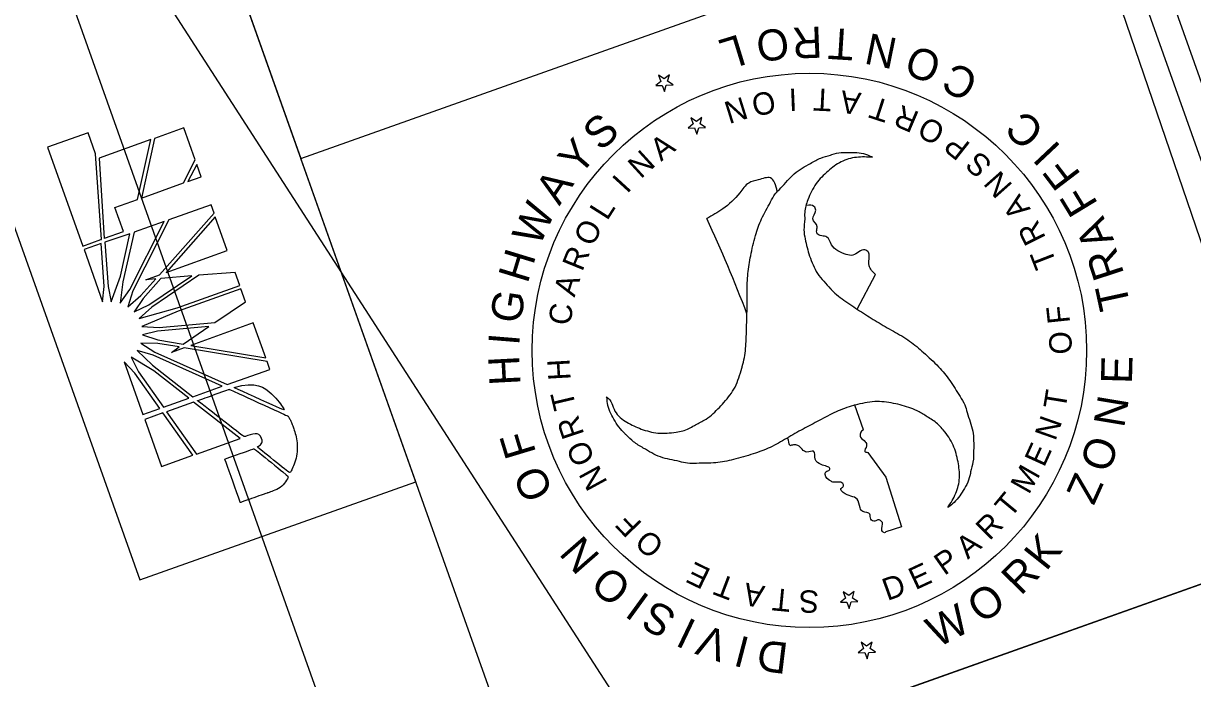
# Model space of a CAD drawing. Extents: x 1615843 to 1618439, y 899470 to 903922.
# Drawn here: x 1616766.4 to 1616956.1, y 903530.7 to 903637 of the extents above; entities that cross this region are included whole.
import ezdxf

# ---------------------------------------------------------------- set-up
doc = ezdxf.new("R2010")
doc.units = 0
for name, color, linetype in [('Default', 7, 'Continuous'), ('DEV BORDER CELL', 7, 'Continuous'), ('DEV DOT SWIRL SEAL CELL', 7, 'Continuous'), ('Scratch_Level_0', 7, 'Continuous'), ('Scratch_Level_5', 7, 'Continuous'), ('Sheet Clip Boundary CELL', 7, 'Continuous'), ('Sheet Plan CELL', 7, 'Continuous'), ('Text', 7, 'Continuous')]:
    doc.layers.add(name, color=color, linetype=linetype)

msp = doc.modelspace()

# ---------------------------------------------------------------- linework, layer by layer
at = {"layer": 'Default'}
for p, q in [((1616776.9, 903619.28), (1616770.33, 903616.94)), ((1616778.12, 903615.87), (1616776.9, 903619.28)), ((1616792.44, 903620.07), (1616787.7, 903618.38)), ((1616794.28, 903614.89), (1616792.44, 903620.07)), ((1616770.33, 903616.94), (1616776.05, 903600.9)), ((1616787.11, 903618.17), (1616778.69, 903615.17)), ((1616784.92, 903608.48), (1616787.11, 903618.17)), ((1616787.7, 903618.38), (1616785.55, 903608.7)), ((1616779.08, 903601.99), (1616778.12, 903615.87)), ((1616778.69, 903615.17), (1616779.53, 903602.15)), ((1616792.37, 903611.14), (1616794.28, 903614.89)), ((1616794.55, 903614.14), (1616793.11, 903611.4)), ((1616795.25, 903612.16), (1616794.55, 903614.14)), ((1616793.11, 903611.4), (1616795.25, 903612.16)), ((1616785.55, 903608.7), (1616792.37, 903611.14)), ((1616781.26, 903607.17), (1616784.92, 903608.48)), ((1616796.88, 903607.61), (1616790.03, 903605.17)), ((1616797.36, 903606.26), (1616796.88, 903607.61)), ((1616782.65, 903603.26), (1616781.26, 903607.17)), ((1616788.48, 903596.23), (1616797.36, 903606.26)), ((1616797.54, 903605.62), (1616789.57, 903596.62)), ((1616799.49, 903600.16), (1616797.54, 903605.62)), ((1616783.68, 903593.85), (1616789.24, 903604.88)), ((1616790.03, 903605.17), (1616784.18, 903593.65)), ((1616789.24, 903604.88), (1616784.36, 903603.14)), ((1616776.05, 903600.9), (1616778.99, 903601.95)), ((1616778.99, 903601.95), (1616779.08, 903601.99)), ((1616779.53, 903602.15), (1616779.58, 903602.17)), ((1616779.58, 903602.17), (1616782.65, 903603.26)), ((1616783.68, 903602.9), (1616779.62, 903601.51)), ((1616782.16, 903596.01), (1616783.68, 903602.9)), ((1616784.36, 903603.14), (1616782.53, 903595.1)), ((1616779.04, 903601.3), (1616776.3, 903600.33)), ((1616776.3, 903600.33), (1616779.27, 903591.86)), ((1616779.52, 903594.35), (1616779.04, 903601.3)), ((1616779.62, 903601.51), (1616780.15, 903594.34)), ((1616789.57, 903596.62), (1616799.49, 903600.16)), ((1616786.25, 903595.44), (1616788.48, 903596.23)), ((1616786.76, 903591.35), (1616793.76, 903596.07)), ((1616794.85, 903596.18), (1616787.27, 903591)), ((1616793.76, 903596.07), (1616788.69, 903595.64)), ((1616800.75, 903596.62), (1616794.85, 903596.18)), ((1616801.51, 903594.51), (1616800.75, 903596.62)), ((1616779.27, 903591.86), (1616779.52, 903594.35)), ((1616780.15, 903594.34), (1616780.68, 903591.88)), ((1616780.68, 903591.88), (1616782.16, 903596.01)), ((1616782.53, 903595.1), (1616782.11, 903591.63)), ((1616785.45, 903592.87), (1616787.9, 903595.59)), ((1616788.69, 903595.64), (1616785.82, 903592.39)), ((1616787.9, 903595.59), (1616786.25, 903595.44)), ((1616791.34, 903590.88), (1616801.51, 903594.51)), ((1616782.11, 903591.63), (1616783.68, 903593.85)), ((1616784.18, 903593.65), (1616783.34, 903591.07)), ((1616783.34, 903591.07), (1616785.45, 903592.87)), ((1616785.82, 903592.39), (1616784.41, 903590.23)), ((1616801.7, 903593.97), (1616791.53, 903590.34)), ((1616802.44, 903591.88), (1616801.7, 903593.97)), ((1616784.41, 903590.23), (1616786.76, 903591.35)), ((1616787.27, 903591), (1616785.18, 903589.13)), ((1616785.18, 903589.13), (1616791.34, 903590.88)), ((1616797.46, 903588.48), (1616802.44, 903591.88)), ((1616791.53, 903590.34), (1616785.63, 903587.87)), ((1616788.45, 903587.69), (1616797.46, 903588.48)), ((1616785.63, 903587.87), (1616788.45, 903587.69)), ((1616788.17, 903587.11), (1616785.74, 903586.49)), ((1616796.49, 903587.85), (1616788.17, 903587.11)), ((1616792.34, 903585), (1616796.49, 903587.85)), ((1616803.71, 903588.44), (1616793.56, 903584.77)), ((1616805.74, 903582.75), (1616803.71, 903588.44)), ((1616785.45, 903585.15), (1616787.73, 903583.68)), ((1616788.22, 903585.09), (1616785.45, 903585.15)), ((1616785.74, 903586.49), (1616788.22, 903585.67)), ((1616788.22, 903585.67), (1616792.34, 903585)), ((1616791.7, 903584.53), (1616788.22, 903585.09)), ((1616793.56, 903584.77), (1616805.74, 903582.75)), ((1616787.58, 903580.65), (1616783.89, 903582.89)), ((1616783.89, 903582.89), (1616785.08, 903580.51)), ((1616787.44, 903583.21), (1616784.85, 903583.94)), ((1616784.85, 903583.94), (1616787.36, 903581.56)), ((1616798.67, 903578.15), (1616787.44, 903583.21)), ((1616787.73, 903583.68), (1616799.48, 903578.44)), ((1616790.45, 903583.66), (1616791.7, 903584.53)), ((1616792.47, 903584.38), (1616790.45, 903583.66)), ((1616805.95, 903582.16), (1616792.47, 903584.38)), ((1616784.49, 903580.3), (1616782.74, 903582.14)), ((1616782.74, 903582.14), (1616785.8, 903573.56)), ((1616787.36, 903581.56), (1616793.91, 903576.45)), ((1616799.48, 903578.44), (1616806.4, 903580.9)), ((1616806.4, 903580.9), (1616805.95, 903582.16)), ((1616788.53, 903574.53), (1616784.49, 903580.3)), ((1616785.08, 903580.51), (1616789.12, 903574.74)), ((1616793.25, 903576.22), (1616787.58, 903580.65)), ((1616793.91, 903576.45), (1616798.67, 903578.15)), ((1616789.12, 903574.74), (1616793.25, 903576.22)), ((1616794.03, 903575.6), (1616789.62, 903574.03)), ((1616801.58, 903569.7), (1616794.03, 903575.6)), ((1616785.8, 903573.56), (1616788.53, 903574.53)), ((1616789.06, 903573.83), (1616786.12, 903572.78)), ((1616793.9, 903566.96), (1616789.06, 903573.83)), ((1616789.62, 903574.03), (1616794.47, 903567.16)), ((1616786.12, 903572.78), (1616788.84, 903565.15)), ((1616794.47, 903567.16), (1616801.58, 903569.7)), ((1616788.84, 903565.15), (1616793.9, 903566.96))]:
    msp.add_line(p, q, dxfattribs=at)
for points in [[(1616785.55, 903608.7), (1616792.37, 903611.14), (1616794.28, 903614.89), (1616792.44, 903620.07), (1616787.7, 903618.38), (1616785.55, 903608.7), (1616785.55, 903608.7)], [(1616779.53, 903602.15), (1616779.58, 903602.17), (1616782.65, 903603.26), (1616781.26, 903607.17), (1616784.92, 903608.48), (1616787.11, 903618.17), (1616778.69, 903615.17), (1616779.53, 903602.15)], [(1616795.25, 903612.16), (1616795.25, 903612.16), (1616794.55, 903614.14), (1616793.11, 903611.4), (1616795.25, 903612.16)], [(1616783.34, 903591.07), (1616785.45, 903592.87), (1616787.9, 903595.59), (1616786.25, 903595.44), (1616788.48, 903596.23), (1616797.36, 903606.26), (1616796.88, 903607.61), (1616790.03, 903605.17), (1616784.18, 903593.65), (1616783.34, 903591.07)], [(1616799.49, 903600.16), (1616797.54, 903605.62), (1616789.57, 903596.62), (1616799.49, 903600.16)], [(1616782.11, 903591.63), (1616783.68, 903593.85), (1616789.24, 903604.88), (1616784.36, 903603.14), (1616782.53, 903595.1), (1616782.11, 903591.63)], [(1616780.68, 903591.88), (1616782.16, 903596.01), (1616783.68, 903602.9), (1616779.62, 903601.51), (1616780.15, 903594.34), (1616780.68, 903591.88)], [(1616779.52, 903594.35), (1616779.04, 903601.3), (1616776.3, 903600.33), (1616779.27, 903591.86), (1616779.52, 903594.35)], [(1616784.41, 903590.23), (1616786.76, 903591.35), (1616793.76, 903596.07), (1616788.69, 903595.64), (1616785.82, 903592.39), (1616784.41, 903590.23)], [(1616785.18, 903589.13), (1616791.34, 903590.88), (1616801.51, 903594.51), (1616800.75, 903596.62), (1616794.85, 903596.18), (1616787.27, 903591), (1616785.18, 903589.13)], [(1616788.45, 903587.69), (1616797.46, 903588.48), (1616802.44, 903591.88), (1616801.7, 903593.97), (1616791.53, 903590.34), (1616785.63, 903587.87), (1616788.45, 903587.69)], [(1616785.74, 903586.49), (1616788.22, 903585.67), (1616792.34, 903585), (1616796.49, 903587.85), (1616788.17, 903587.11), (1616785.74, 903586.49)], [(1616805.74, 903582.75), (1616803.71, 903588.44), (1616793.56, 903584.77), (1616805.74, 903582.75)], [(1616785.45, 903585.15), (1616787.73, 903583.68), (1616799.48, 903578.44), (1616806.4, 903580.9), (1616805.95, 903582.16), (1616792.47, 903584.38), (1616790.45, 903583.66), (1616791.7, 903584.53), (1616788.22, 903585.09), (1616785.45, 903585.15)], [(1616789.12, 903574.74), (1616793.25, 903576.22), (1616787.58, 903580.65), (1616783.89, 903582.89), (1616785.08, 903580.51), (1616789.12, 903574.74)], [(1616793.91, 903576.45), (1616798.67, 903578.15), (1616787.44, 903583.21), (1616784.85, 903583.94), (1616787.36, 903581.56), (1616793.91, 903576.45)], [(1616784.49, 903580.3), (1616782.74, 903582.14), (1616785.8, 903573.56), (1616788.53, 903574.53), (1616784.49, 903580.3)], [(1616801.58, 903569.7), (1616794.03, 903575.6), (1616789.62, 903574.03), (1616794.47, 903567.16), (1616801.58, 903569.7)], [(1616793.9, 903566.96), (1616789.06, 903573.83), (1616786.12, 903572.78), (1616788.84, 903565.15), (1616793.9, 903566.96)]]:
    msp.add_lwpolyline(points, dxfattribs=at)
for points in [[(1616800.6, 903577.94), (1616800.6, 903577.94), (1616808.85, 903574.19), (1616808.85, 903574.19), (1616807.09, 903576.84), (1616804.14, 903579.05), (1616800.6, 903577.94)], [(1616800.6, 903577.94), (1616800.6, 903577.94), (1616808.85, 903574.19), (1616808.85, 903574.19), (1616807.09, 903576.84), (1616804.14, 903579.05), (1616800.6, 903577.94)], [(1616805.06, 903569.7), (1616805.22, 903569.25), (1616805.11, 903568.77), (1616804.32, 903568.31), (1616804.32, 903568.31), (1616809.66, 903564.04), (1616809.66, 903564.04), (1616810.83, 903566.36), (1616810.93, 903569.43), (1616810.12, 903571.7), (1616809.91, 903572.3), (1616809.69, 903572.73), (1616809.34, 903573.32), (1616809.34, 903573.32), (1616799.8, 903577.66), (1616799.8, 903577.66), (1616799.8, 903577.66), (1616794.66, 903575.83), (1616794.66, 903575.83), (1616794.66, 903575.83), (1616802.23, 903569.93), (1616802.23, 903569.93), (1616804.15, 903570.61), (1616804.83, 903570.33), (1616805.06, 903569.7)], [(1616805.06, 903569.7), (1616805.22, 903569.25), (1616805.11, 903568.77), (1616804.32, 903568.31), (1616804.32, 903568.31), (1616809.66, 903564.04), (1616809.66, 903564.04), (1616810.83, 903566.36), (1616810.93, 903569.43), (1616810.12, 903571.7), (1616809.91, 903572.3), (1616809.69, 903572.73), (1616809.34, 903573.32), (1616809.34, 903573.32), (1616799.8, 903577.66), (1616799.8, 903577.66), (1616799.8, 903577.66), (1616794.66, 903575.83), (1616794.66, 903575.83), (1616794.66, 903575.83), (1616802.23, 903569.93), (1616802.23, 903569.93), (1616804.15, 903570.61), (1616804.83, 903570.33), (1616805.06, 903569.7)], [(1616799.09, 903566.34), (1616799.09, 903566.34), (1616801.61, 903559.28), (1616801.61, 903559.28), (1616801.61, 903559.28), (1616806.03, 903560.86), (1616806.03, 903560.86), (1616806.03, 903560.86), (1616806.49, 903561.02), (1616806.49, 903561.02), (1616807.88, 903561.52), (1616808.81, 903562.36), (1616809.44, 903563.49), (1616809.44, 903563.49), (1616803.85, 903568.04), (1616803.76, 903568.01), (1616803.76, 903568.01), (1616799.09, 903566.34), (1616799.09, 903566.34)], [(1616799.09, 903566.34), (1616799.09, 903566.34), (1616801.61, 903559.28), (1616801.61, 903559.28), (1616801.61, 903559.28), (1616806.03, 903560.86), (1616806.03, 903560.86), (1616806.03, 903560.86), (1616806.49, 903561.02), (1616806.49, 903561.02), (1616807.88, 903561.52), (1616808.81, 903562.36), (1616809.44, 903563.49), (1616809.44, 903563.49), (1616803.85, 903568.04), (1616803.76, 903568.01), (1616803.76, 903568.01), (1616799.09, 903566.34), (1616799.09, 903566.34)]]:
    msp.add_open_spline(points, degree=3, dxfattribs=at)
at = {"layer": 'DEV BORDER CELL'}
msp.add_line((1616871.74, 903515.59), (1616979.16, 903553.77), dxfattribs=at)
for points in [[(1615874.87, 903538.12), (1616377.33, 902124.77), (1617366.67, 902476.49), (1616864.22, 903889.84)], [(1616732.36, 903837.5), (1616811.41, 903615.13), (1616940.97, 903661.19), (1616861.92, 903883.55)], [(1616849.6, 903507.72), (1616811.41, 903615.13), (1616940.97, 903661.19), (1616979.16, 903553.77)], [(1616916.61, 903319.23), (1616849.6, 903507.72), (1616979.16, 903553.77), (1617046.17, 903365.29)]]:
    msp.add_lwpolyline(points, close=True, dxfattribs=at)
at = {"layer": 'DEV DOT SWIRL SEAL CELL'}
for p, q in [((1616869.43, 903628.65), (1616869.8, 903627.63)), ((1616870.34, 903628.03), (1616869.43, 903628.65)), ((1616871.21, 903628.69), (1616870.34, 903628.03)), ((1616870.9, 903627.64), (1616871.21, 903628.69)), ((1616869.8, 903627.63), (1616868.98, 903626.95)), ((1616868.98, 903626.95), (1616870.03, 903626.98)), ((1616870.03, 903626.98), (1616870.39, 903625.96)), ((1616870.39, 903625.96), (1616870.7, 903627.01)), ((1616870.7, 903627.01), (1616871.79, 903627.06)), ((1616871.79, 903627.06), (1616870.9, 903627.64)), ((1616875.06, 903620.71), (1616874.24, 903620.04)), ((1616874.7, 903621.73), (1616875.06, 903620.71)), ((1616875.6, 903621.12), (1616874.7, 903621.73)), ((1616876.47, 903621.77), (1616875.6, 903621.12)), ((1616876.17, 903620.72), (1616876.47, 903621.77)), ((1616877.05, 903620.14), (1616876.17, 903620.72)), ((1616874.24, 903620.04), (1616875.29, 903620.07)), ((1616875.29, 903620.07), (1616875.65, 903619.05)), ((1616875.65, 903619.05), (1616875.96, 903620.1)), ((1616875.96, 903620.1), (1616877.05, 903620.14)), ((1616901.69, 903590.66), (1616904.65, 903596.28)), ((1616902.68, 903571.11), (1616901.3, 903575.09)), ((1616903.38, 903567.43), (1616906.33, 903563.38)), ((1616906.33, 903563.38), (1616908.84, 903555.37)), ((1616908.84, 903555.37), (1616906.31, 903554.56)), ((1616899.77, 903543.78), (1616898.95, 903543.1)), ((1616898.95, 903543.1), (1616900, 903543.14)), ((1616899.41, 903544.8), (1616899.77, 903543.78)), ((1616900.31, 903544.18), (1616899.41, 903544.8)), ((1616900, 903543.14), (1616900.36, 903542.11)), ((1616901.19, 903544.83), (1616900.31, 903544.18)), ((1616900.36, 903542.11), (1616900.67, 903543.16)), ((1616900.67, 903543.16), (1616901.76, 903543.21)), ((1616900.88, 903543.79), (1616901.19, 903544.83)), ((1616901.76, 903543.21), (1616900.88, 903543.79)), ((1616902.67, 903535.6), (1616901.84, 903534.92)), ((1616903.2, 903536), (1616902.3, 903536.62)), ((1616902.3, 903536.62), (1616902.67, 903535.6)), ((1616903.2, 903536), (1616902.3, 903536.62)), ((1616904.08, 903536.66), (1616903.2, 903536)), ((1616904.08, 903536.65), (1616903.2, 903536)), ((1616903.77, 903535.61), (1616904.08, 903536.66)), ((1616903.77, 903535.61), (1616904.08, 903536.65)), ((1616904.66, 903535.03), (1616903.77, 903535.61)), ((1616901.84, 903534.92), (1616902.89, 903534.95)), ((1616902.89, 903534.95), (1616903.26, 903533.93)), ((1616903.26, 903533.93), (1616903.57, 903534.98)), ((1616903.57, 903534.98), (1616904.66, 903535.03))]:
    msp.add_line(p, q, dxfattribs=at)
for start, end in [(20.7742, 24.8942), (15.2492, 15.5469)]:
    msp.add_arc((1616665.76, 903507.19), 233.19, start, end, dxfattribs=at)
for points in [[(1616860.97, 903576.42), (1616861.07, 903576.37), (1616862.38, 903574.11), (1616864.31, 903572.31), (1616866.63, 903571.22), (1616869.34, 903570.57), (1616872.31, 903570.71), (1616874.36, 903571.29), (1616875.25, 903571.81), (1616876.84, 903572.63), (1616878.02, 903573.48), (1616880.05, 903575.54), (1616881.85, 903578.03), (1616882.95, 903581.1), (1616883.03, 903581.36), (1616883.56, 903584.28), (1616883.71, 903587.38), (1616883.8, 903590.32), (1616883.82, 903593.38), (1616883.94, 903596.44), (1616884.39, 903599.33), (1616885.16, 903602.6), (1616886.16, 903605.32), (1616887.61, 903608.06), (1616888.37, 903609.36), (1616889.28, 903610.33), (1616891.45, 903612.64), (1616894.1, 903614.32), (1616895.79, 903615.18), (1616897.32, 903615.67), (1616897.58, 903615.76), (1616900.56, 903616.11), (1616903.33, 903615.7), (1616904.17, 903615.31)], [(1616904.17, 903615.31), (1616901.56, 903615.3), (1616899.06, 903614.55), (1616896.94, 903613.06), (1616895.02, 903611.03), (1616893.67, 903608.41), (1616893.15, 903606.35), (1616893.15, 903605.3), (1616893.03, 903603.55), (1616893.22, 903602.05), (1616893.95, 903599.29), (1616895.24, 903596.47), (1616897.34, 903593.99), (1616897.52, 903593.8), (1616899.82, 903591.89), (1616902.39, 903590.21), (1616904.89, 903588.62), (1616907.55, 903587.08), (1616910.17, 903585.48), (1616912.42, 903583.63), (1616914.87, 903581.31), (1616916.71, 903579.09), (1616918.35, 903576.48), (1616919.11, 903575.15), (1616919.5, 903573.89), (1616920.4, 903570.88), (1616920.56, 903567.72), (1616920.45, 903565.86), (1616920.07, 903564.27), (1616920.03, 903564), (1616918.87, 903561.25), (1616917.14, 903559.07), (1616916.35, 903558.47)], [(1616888.7, 903609.74), (1616887.59, 903611.96), (1616885.63, 903611.65), (1616884.07, 903611.13), (1616882.63, 903609.53), (1616879.86, 903606.93), (1616877.28, 903605.35)], [(1616904.65, 903596.28), (1616903.6, 903597.71), (1616903.63, 903599.22), (1616903.51, 903599.9), (1616902.92, 903600.29), (1616900.98, 903599.42), (1616899.89, 903599.54), (1616897.52, 903601.13), (1616896.76, 903602.35), (1616895.18, 903602.9), (1616895.07, 903603.31), (1616895.2, 903604.05), (1616894.45, 903605.31), (1616894.94, 903606.71), (1616894.66, 903607.33), (1616893.47, 903607.49)], [(1616916.35, 903558.47), (1616917.66, 903560.79), (1616918.25, 903563.31), (1616918.02, 903565.88), (1616917.23, 903568.59), (1616915.63, 903571.07), (1616914.08, 903572.54), (1616913.21, 903573.08), (1616911.7, 903574.03), (1616910.36, 903574.61), (1616907.57, 903575.38), (1616904.51, 903575.66), (1616901.32, 903575.1), (1616901.06, 903575.03), (1616898.24, 903574), (1616895.51, 903572.6), (1616892.9, 903571.22), (1616890.22, 903569.7), (1616887.55, 903568.24), (1616884.81, 903567.2), (1616881.59, 903566.26), (1616878.72, 903565.75), (1616875.62, 903565.65), (1616874.13, 903565.66), (1616872.84, 903565.94), (1616869.75, 903566.69), (1616866.97, 903568.13), (1616865.4, 903569.16), (1616864.21, 903570.25), (1616864.01, 903570.44), (1616862.19, 903572.81), (1616861.16, 903575.4), (1616861.07, 903576.37)], [(1616902.68, 903571.11), (1616902.18, 903570.57), (1616902.22, 903569.87), (1616902.98, 903569.15), (1616903.19, 903568.5), (1616902.91, 903567.59), (1616903.38, 903567.43)], [(1616906.31, 903554.56), (1616906.1, 903554.39), (1616905.69, 903554.73), (1616905.75, 903556.07), (1616905.03, 903556.47), (1616904.54, 903556.27), (1616903.86, 903556.57), (1616903.74, 903557.42), (1616902.57, 903557.82), (1616902.15, 903558.42), (1616901.65, 903559.83), (1616899.38, 903560.91), (1616899.02, 903561.56), (1616899.41, 903561.91), (1616899.34, 903562.36), (1616897.69, 903562.62), (1616897.44, 903562.74), (1616896.45, 903563.83), (1616896.59, 903564.27), (1616897.17, 903564.59), (1616897.21, 903564.82), (1616896.76, 903565.14), (1616895.81, 903565.46), (1616894.87, 903566.32), (1616894.6, 903567.61), (1616893.51, 903567.46), (1616892.04, 903568.56), (1616891.35, 903568.64), (1616890.73, 903568.51)]]:
    msp.add_spline(points, degree=3, dxfattribs=at)
at = {"layer": 'Scratch_Level_0'}
msp.add_lwpolyline([(1615938.73, 903507.75), (1616407.69, 902188.63), (1617302.81, 902506.85), (1617008.42, 903334.93), (1616896.98, 903295.32), (1616722.42, 903786.36)], close=True, dxfattribs=at)
at = {"layer": 'Scratch_Level_5'}
for points in [[(1616347.43, 902358.15), (1615993.9, 903352.57), (1616755.41, 903693.55), (1617118.27, 903131.4), (1617302.81, 902506.85), (1616959.09, 902384.66)], [(1616705.54, 902373.67), (1616699.85, 902458.96), (1616686.62, 902573.2), (1616667.04, 902687.93), (1616638.01, 902809.43), (1616596.83, 902943.32), (1616588.98, 902949.04), (1616499.35, 903201.92), (1616504.06, 903203.6), (1616506.92, 903204.49), (1616400, 903496.37), (1616388.07, 903529.07), (1616755.41, 903693.55), (1617118.27, 903131.4), (1617302.81, 902506.85), (1616959.09, 902384.66)]]:
    msp.add_lwpolyline(points, close=True, dxfattribs=at)
at = {"layer": 'Sheet Clip Boundary CELL'}
msp.add_lwpolyline([(1616920.55, 902382.99), (1616489.91, 902364.33), (1616361.78, 902925.96), (1616113.49, 903406.12), (1616903.33, 903759.78), (1617118.27, 903131.4), (1617236.29, 902693.96), (1617083.45, 902390.05)], close=True, dxfattribs=at)
at = {"layer": 'Sheet Plan CELL'}
msp.add_lwpolyline([(1616687.59, 903821.58), (1616785.29, 903546.76), (1616830.06, 903562.67), (1616732.36, 903837.5)], close=True, dxfattribs=at)
at = {"layer": 'Text'}
msp.add_circle((1616893.92, 903583.97), 44.97, dxfattribs=at)

# ---------------------------------------------------------------- texts
at = {"layer": 'DEV DOT SWIRL SEAL CELL'}
for s, height, rotation, p in [('I', 3.63, 182.3414, (1616891.85, 903626.46)), ('T', 3.63, 177.2633, (1616897.6, 903626.38)), ('N', 3.63, 197.3036, (1616883.15, 903625.18)), ('O', 3.63, 192.4976, (1616887.95, 903626.22)), ('A', 3.63, 172.1852, (1616902.43, 903625.74)), ('T', 3.63, 162.0291, (1616907.32, 903624.34)), ('R', 3.63, 156.951, (1616911.94, 903622.53)), ('S', 5.04, 42.7956, (1616860.1, 903616.15)), ('O', 3.63, 151.8729, (1616916.19, 903620.3)), ('Y', 5.04, 49.3191, (1616856.59, 903612.11)), ('A', 3.63, 37.344, (1616869.85, 903614.56)), ('P', 3.63, 141.7167, (1616920.22, 903617.41)), ('N', 3.63, 42.4221, (1616866.57, 903611.7)), ('S', 3.63, 136.6386, (1616923.77, 903614.29)), ('A', 5.04, 56.3469, (1616853.36, 903607.33)), ('I', 3.63, 47.5002, (1616864.34, 903609.29)), ('N', 3.63, 131.5606, (1616927.02, 903610.76)), ('A', 3.63, 126.4825, (1616929.86, 903606.91)), ('W', 5.04, 65.384, (1616850.1, 903600.67)), ('L', 3.63, 57.6563, (1616861.11, 903604.91)), ('O', 3.63, 62.7344, (1616858.73, 903600.65)), ('R', 3.63, 116.3263, (1616932.35, 903602.22)), ('H', 5.04, 73.0339, (1616848.19, 903594.69)), ('R', 3.63, 67.8125, (1616857.06, 903596.65)), ('T', 3.63, 111.2482, (1616934.08, 903598.07)), ('A', 3.63, 72.8906, (1616855.82, 903592.51)), ('G', 5.04, 81.0874, (1616847.06, 903588.18)), ('C', 3.63, 83.0467, (1616855.19, 903587.93)), ('F', 3.63, 96.014, (1616936.22, 903588.47)), ('O', 3.63, 90.9359, (1616936.48, 903583.34)), ('I', 5.04, 85.3747, (1616846.83, 903584.67)), ('H', 5.04, 93.0247, (1616847.08, 903578.4)), ('H', 3.63, 93.2029, (1616855.2, 903579.2)), ('T', 3.63, 80.7797, (1616935.44, 903574.26)), ('R', 3.63, 108.4372, (1616857.43, 903570.36)), ('N', 3.63, 70.6235, (1616933.81, 903569.17)), ('F', 5.04, 106.8282, (1616849.62, 903567.38)), ('O', 3.63, 113.5153, (1616859.19, 903566.23)), ('E', 3.63, 65.5455, (1616931.98, 903564.89)), ('O', 5.04, 115.3356, (1616852.48, 903561.01)), ('N', 3.63, 118.5933, (1616861.25, 903562.57)), ('M', 3.63, 60.4674, (1616929.5, 903560.47)), ('T', 3.63, 50.3112, (1616926.52, 903556.63)), ('F', 3.63, 133.8276, (1616866.94, 903555.86)), ('R', 3.63, 45.2331, (1616923.13, 903553)), ('O', 3.63, 138.9057, (1616870.57, 903552.68)), ('N', 5.04, 131.1567, (1616860.15, 903550.58)), ('A', 3.63, 40.155, (1616919.61, 903549.98)), ('P', 3.63, 35.0769, (1616915.81, 903547.35)), ('E', 3.63, 154.1399, (1616878.14, 903548.36)), ('E', 3.63, 24.9208, (1616911.11, 903545.04)), ('O', 5.04, 139.6642, (1616865.37, 903545.95)), ('T', 3.63, 159.218, (1616882.22, 903546.78)), ('D', 3.63, 19.8427, (1616906.56, 903543.3)), ('A', 3.63, 169.3742, (1616886.83, 903545.7)), ('T', 3.63, 174.4523, (1616891.05, 903545.14)), ('S', 3.63, 179.5304, (1616895.49, 903545.03)), ('I', 5.04, 143.9515, (1616868.25, 903543.93)), ('S', 5.04, 150.1555, (1616872.67, 903541.39)), ('I', 5.04, 154.4429, (1616875.87, 903539.93)), ('V', 5.04, 161.1513, (1616881.07, 903538.12)), ('I', 5.04, 165.4386, (1616884.49, 903537.29)), ('D', 5.04, 173.0297, (1616890.66, 903536.46))]:
    msp.add_text(s, height=height, rotation=rotation, dxfattribs=at).set_placement(p)
at = {"layer": 'Text'}
for s, height, rotation, p in [('O', 5.04, 188.5603, (1616890.17, 903636.43)), ('R', 5.04, 182.3225, (1616895.89, 903636.52)), ('T', 5.04, 176.4517, (1616901.25, 903636.05)), ('L', 5.04, 196.9997, (1616882.51, 903635.31)), ('N', 5.04, 168.4627, (1616908.42, 903634.52)), ('O', 5.04, 160.0233, (1616915.68, 903631.84)), ('C', 5.04, 152.6514, (1616921.65, 903628.65)), ('C', 5.04, 137.574, (1616932.32, 903619.9)), ('I', 5.04, 133.3209, (1616934.88, 903616.96)), ('F', 5.04, 127.3333, (1616938.09, 903612.5)), ('F', 5.04, 121.3457, (1616940.83, 903607.74)), ('A', 5.04, 114.3741, (1616943.37, 903601.87)), ('R', 5.04, 108.1363, (1616945.02, 903596.39)), ('T', 5.04, 102.2655, (1616946.02, 903591.1)), ('E', 5.04, 88.5223, (1616946.23, 903578.51)), ('T', 3.63, 103.3591, (1616856.09, 903574.79)), ('N', 5.04, 80.5333, (1616944.96, 903571.3)), ('O', 5.04, 72.094, (1616942.55, 903563.94)), ('Z', 5.04, 65.7394, (1616940.03, 903558.68)), ('K', 5.04, 51.3625, (1616932.31, 903548.02)), ('R', 5.04, 45.1247, (1616928.18, 903544.06)), ('O', 5.04, 36.6854, (1616921.95, 903539.47)), ('W', 5.04, 27.7207, (1616914.67, 903535.64))]:
    msp.add_text(s, height=height, rotation=rotation, dxfattribs=at).set_placement(p)

doc.saveas('drawing.dxf')
